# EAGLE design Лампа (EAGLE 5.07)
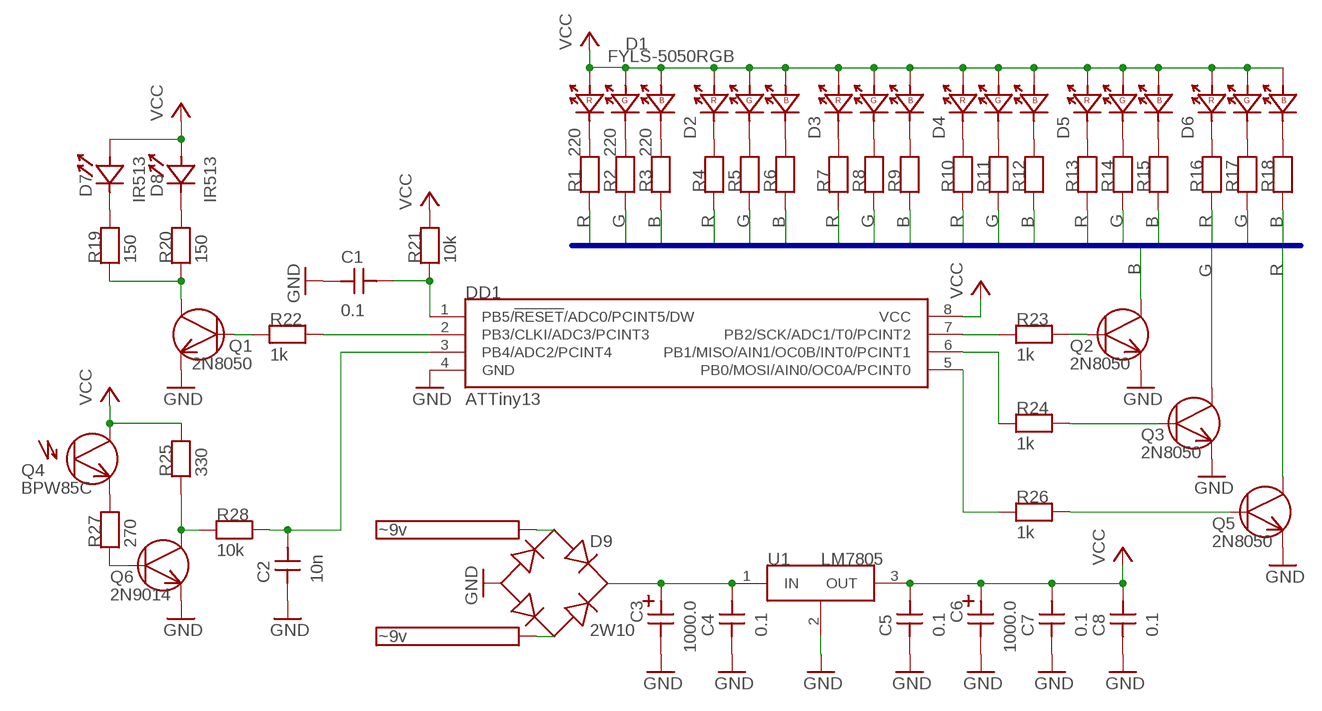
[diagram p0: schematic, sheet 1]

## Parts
C1  0.1  CAPACITOR_0805  [0805]
C2  10n  CAPACITOR_0805  [0805]
C3  1000.0  CAPACITOR_POLAR5,08_H1  [CAPACITOR_POLAR_5,08_H1]
C4  0.1  CAPACITOR_0805  [0805]
C5  0.1  CAPACITOR_0805  [0805]
C6  1000.0  CAPACITOR_POLAR5,08_H2  [CAPACITOR_POLAR_5,08_H2]
C7  0.1  CAPACITOR_0805  [0805]
C8  0.1  CAPACITOR_0805  [0805]
D1  FYLS-5050RGB  LED_FYLS-5050RGB  [LED_FYLS-5050RGB]
D2  LED_FYLS-5050RGB  [LED_FYLS-5050RGB]
D3  LED_FYLS-5050RGB  [LED_FYLS-5050RGB]
D4  LED_FYLS-5050RGB  [LED_FYLS-5050RGB]
D5  LED_FYLS-5050RGB  [LED_FYLS-5050RGB]
D6  LED_FYLS-5050RGB  [LED_FYLS-5050RGB]
D7  IR513  LED_5MM  [LED_5MM]
D8  IR513  LED_5MM  [LED_5MM]
D9  2W10  DIODE_BRIDGE  [DIODE_BRIDGE]
DD1  ATTiny13  ATTINY13  [DIL08]
PIN1  ~9v  PIN_NONAME  [PIN]
PIN2  ~9v  PIN_NONAME  [PIN]
Q1  2N8050  TRANSISTOR_NPN_TO92_EBC  [TO92]
Q2  2N8050  TRANSISTOR_NPN_TO92_EBC  [TO92]
Q3  2N8050  TRANSISTOR_NPN_TO92_EBC  [TO92]
Q4  BPW85C  BPW85  [BPW85]
Q5  2N8050  TRANSISTOR_NPN_TO92_EBC  [TO92]
Q6  2N9014  TRANSISTOR_NPN_TO92_EBC  [TO92]
R1  220  RESISTOR_0805  [0805]
R2  220  RESISTOR_0805  [0805]
R3  220  RESISTOR_0805  [0805]
R4  RESISTOR_0805  [0805]
R5  RESISTOR_0805  [0805]
R6  RESISTOR_0805  [0805]
R7  RESISTOR_0805  [0805]
R8  RESISTOR_0805  [0805]
R9  RESISTOR_0805  [0805]
R10  RESISTOR_0805  [0805]
R11  RESISTOR_0805  [0805]
R12  RESISTOR_0805  [0805]
R13  RESISTOR_0805  [0805]
R14  RESISTOR_0805  [0805]
R15  RESISTOR_0805  [0805]
R16  RESISTOR_0805  [0805]
R17  RESISTOR_0805  [0805]
R18  RESISTOR_0805  [0805]
R19  150  RESISTOR_0805  [0805]
R20  150  RESISTOR_HORIZONTAL  [RESISTOR_HORIZ]
R21  10k  RESISTOR_0805  [0805]
R22  1k  RESISTOR_HORIZONTAL  [RESISTOR_HORIZ]
R23  1k  RESISTOR_VERTICAL  [RESISTOR_VERT]
R24  1k  RESISTOR_VERTICAL  [RESISTOR_VERT]
R25  330  RESISTOR_VERTICAL  [RESISTOR_VERT]
R26  1k  RESISTOR_VERTICAL  [RESISTOR_VERT]
R27  270  RESISTOR_0805  [0805]
R28  10k  RESISTOR_VERTICAL  [RESISTOR_VERT]
U1  LM7805  LM78XX/LM79XX_78XX_D2PACK_2  [D2PACK_2]

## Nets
B: Q2.3(COLLECTOR) R3.1 R6.1 R9.1 R12.1 R15.1 R18.1
G: Q3.3(COLLECTOR) R2.1 R5.1 R8.1 R11.1 R14.1 R17.1
GND: C1.1 C2.1 C3.MINUS C4.1 C5.1 C6.MINUS C7.1 C8.1 D9.- DD1.4(GND) Q1.1(EMITTER) Q2.1(EMITTER) Q3.1(EMITTER) Q5.1(EMITTER) Q6.1(EMITTER) U1.2(GND)
N$1: C1.2 DD1.1(PB5/!RESET!/ADC0/PCINT5/DW) R21.1
N$2: Q1.2(BASE) R22.1
N$3: DD1.2(PB3/CLKI/ADC3/PCINT3) R22.2
N$4: Q1.3(COLLECTOR) R19.1 R20.1
N$5: D7.CATODE R19.2
N$6: D8.CATODE R20.2
N$7: Q4.E(EMITTER) R27.2
N$8: Q6.2(BASE) R27.1
N$9: Q6.3(COLLECTOR) R25.1 R28.1
N$10: D1.RC R1.2
N$11: C2.2 DD1.3(PB4/ADC2/PCINT4) R28.2
N$12: DD1.7(PB2/SCK/ADC1/T0/PCINT2) R23.1
N$13: Q2.2(BASE) R23.2
N$14: DD1.6(PB1/MISO/AIN1/OC0B/INT0/PCINT1) R24.1
N$15: Q3.2(BASE) R24.2
N$16: DD1.5(PB0/MOSI/AIN0/OC0A/PCINT0) R26.1
N$17: Q5.2(BASE) R26.2
N$18: D1.GC R2.2
N$19: D1.BC R3.2
N$20: D2.RC R4.2
N$21: D2.GC R5.2
N$22: D2.BC R6.2
N$23: D3.RC R7.2
N$24: D3.GC R8.2
N$25: D3.BC R9.2
N$26: D4.RC R10.2
N$27: D4.GC R11.2
N$28: D4.BC R12.2
N$29: D5.RC R13.2
N$30: D5.GC R14.2
N$31: D5.BC R15.2
N$32: D6.RC R16.2
N$33: D6.GC R17.2
N$34: D9.AC1 PIN1.P$1
N$35: D9.AC2 PIN2.P$1
N$36: C3.PLUS C4.2 D9.+ U1.1(IN)
N$37: D6.BC R18.2
R: Q5.3(COLLECTOR) R1.1 R4.1 R7.1 R10.1 R13.1 R16.1
VCC: C5.2 C6.PLUS C7.2 C8.2 D1.BA D1.GA D1.RA D2.BA D2.GA D2.RA D3.BA D3.GA D3.RA D4.BA D4.GA D4.RA D5.BA D5.GA D5.RA D6.BA D6.GA D6.RA D7.ANODE D8.ANODE DD1.8(VCC) Q4.C(COLLECTOR) R21.2 R25.2 U1.3(OUT)

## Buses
BUS:R,G,B

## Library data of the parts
C1 C2 C4 C5 C7 C8 = Len9:CAPACITOR
C3 C6 = Len9:CAPACITOR_POLAR
D1-D6 = Len9:LED_FYLS-5050RGB
D7 D8 = Len9:LED
D9 = Len9:DIODE_BRIDGE
DD1 = Len9:ATTINY13
PIN1 PIN2 = Len9:PIN_NONAME
Q1-Q3 Q5 Q6 = Len9:TRANSISTOR_NPN
Q4 = Len9:BPW85
R1-R28 = Len9:RESISTOR
U1 = Len9:LM78XX/LM79XX

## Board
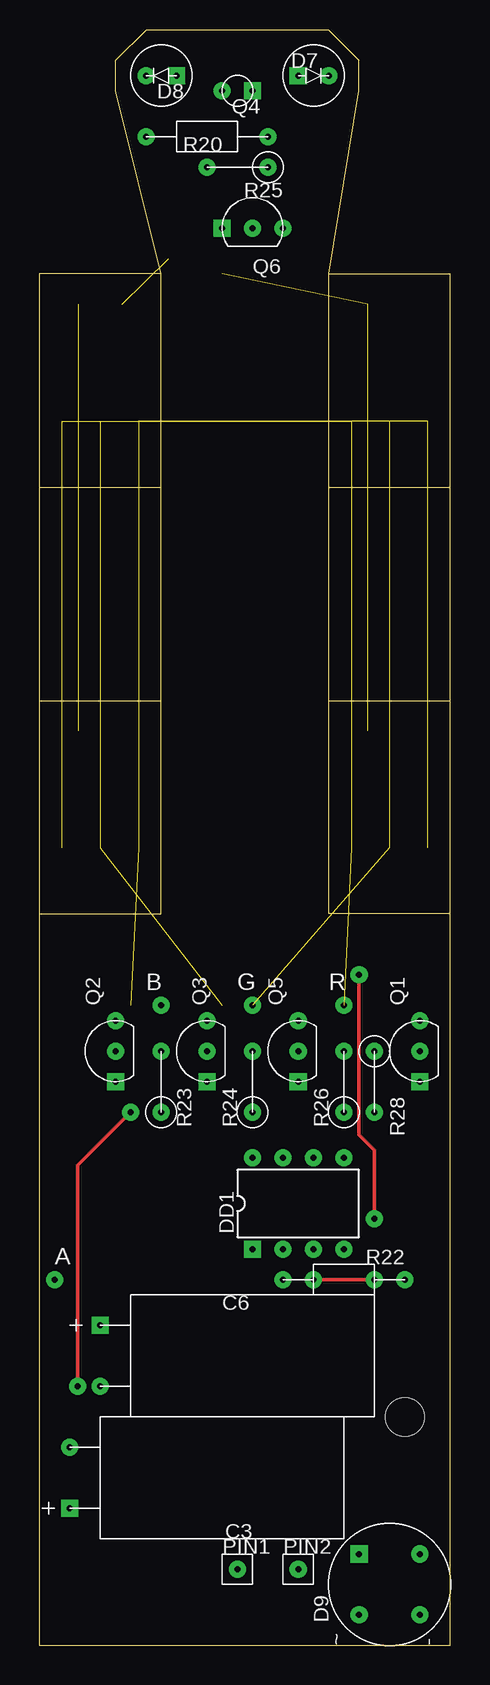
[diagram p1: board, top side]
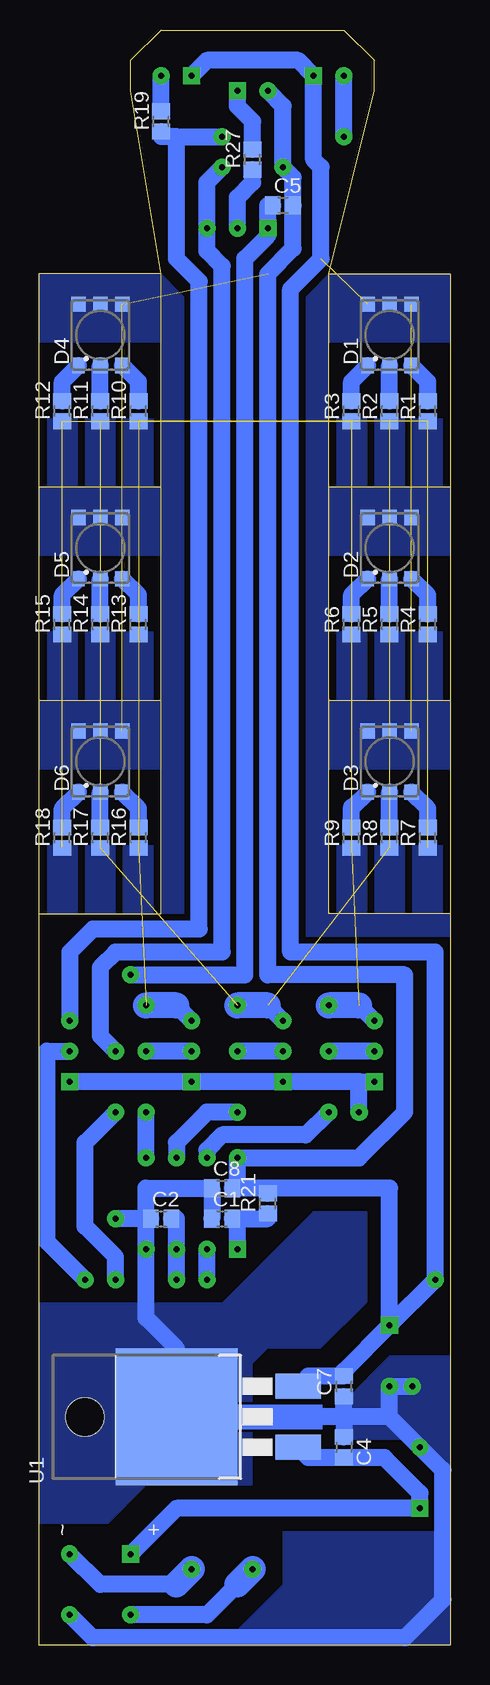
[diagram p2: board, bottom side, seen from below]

Size 34.29 x 134.62 mm. Coordinates in mm from the lower left corner, seen from the top.
Outline: 34.29,60.96 34.29,0 0,0 0,60.96
Outline: 34.29,60.96 34.29,78.74
Outline: 34.29,78.74 34.29,96.52
Outline: 34.29,96.52 34.29,114.3 24.13,114.3
Outline: 0,96.52 0,114.3 10.16,114.3
Outline: 0,96.52 0,78.74
Outline: 0,78.74 0,60.96
Outline: 0,60.96 10.16,60.96 10.16,78.74
Outline: 10.16,78.74 10.16,96.52
Outline: 10.16,96.52 10.16,114.3
Outline: 0,96.52 10.16,96.52
Outline: 0,78.74 10.16,78.74
Outline: 34.29,60.96 24.13,60.96 24.13,78.74
Outline: 24.13,78.74 24.13,96.52
Outline: 24.13,96.52 24.13,114.3
Outline: 24.13,96.52 34.29,96.52
Outline: 24.13,78.74 34.29,78.74
Outline: 10.16,114.3 6.35,129.54 6.35,132.08 8.89,134.62 24.13,134.62 26.67,132.08 26.67,129.54 24.13,114.3
Copper layers (1*16): Top 0.035mm / dielectric 1.5mm / Bottom 0.035mm
Design rules "default *": minimum track width 10mil, minimum drill 24mil, track to track 8mil, track to pad 8mil, pad to pad 8mil, via to via 8mil, smd to smd 8mil, copper to edge 0mil, drill to drill 8mil, minimum pad ring 10mil, minimum via ring 8mil, stop-mask expansion 4mil, vias tented up to drill 0mil, thermal gap 10mil

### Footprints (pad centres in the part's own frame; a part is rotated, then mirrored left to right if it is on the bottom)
0805 = smd 1.3 x 1.5: 1 -0.85,0; 2 0.85,0
CAPACITOR_POLAR_5,08_H1 = drill 0.5 pad 1.422 round: MINUS 2.54,0 | drill 0.5 pad 1.422 square: PLUS -2.54,0
CAPACITOR_POLAR_5,08_H2 = drill 0.5 pad 1.422 round: MINUS 2.54,0 | drill 0.5 pad 1.422 square: PLUS -2.54,0
LED_FYLS-5050RGB = smd 1.27 x 1.2: BA 2.55,1.825; GA 2.55,0; GC -2.55,0; RA 2.55,-1.825; RC -2.55,-1.825 | smd 1.27 x 1.05: BC -2.55,1.825
LED_5MM = drill 0.5 pad 1.422 square: ANODE -1.27,0 | drill 0.5 pad 1.422 round: CATODE 1.27,0
DIODE_BRIDGE = drill 0.5 pad 1.422 square: + 2.54,2.54 | drill 0.5 pad 1.422 round: - -2.54,-2.54; AC1 -2.54,2.54; AC2 2.54,-2.54
DIL08 = drill 0.5 pad 1.422 square: 1 -3.81,-3.81 | drill 0.5 pad 1.422 round: 2 -1.27,-3.81; 3 1.27,-3.81; 4 3.81,-3.81; 5 3.81,3.81; 6 1.27,3.81; 7 -1.27,3.81; 8 -3.81,3.81
PIN = drill 0.5 pad 1.422 round: P$1 0,0
TO92 = drill 0.5 pad 1.422 square: 1 -2.54,0 | drill 0.5 pad 1.422 round: 2 0,0; 3 2.54,0
BPW85 = drill 0.5 pad 1.422 round: C 1.27,0 | drill 0.5 pad 1.422 square: E -1.27,0
RESISTOR_HORIZ = drill 0.5 pad 1.422 round: 1 -5.08,0; 2 5.08,0
RESISTOR_VERT = drill 0.5 pad 1.422 round: 1 -2.54,0; 2 2.54,0
D2PACK_2 = smd 2.083 x 3.81: 1 -2.54,-10.16; 3 2.54,-10.16 | smd 11.43 x 10.16: 2 0,0 | hole 3.2: 0,7.62

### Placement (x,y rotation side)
C1  19.05,35.56 0 bottom
C2  24.13,35.56 0 bottom
C3  2.54,13.97 90 top
C4  8.89,16.51 270 bottom
C5  13.97,120.02 0 bottom
C6  5.08,24.13 270 top
C7  8.89,21.59 90 bottom
C8  19.05,38.1 0 bottom
D1  5.08,109.22 90 bottom
D2  5.08,91.44 90 bottom
D3  5.08,73.66 90 bottom
D4  29.21,109.22 90 bottom
D5  29.21,91.44 90 bottom
D6  29.21,73.66 90 bottom
D7  22.86,130.81 0 top
D8  10.16,130.81 180 top
D9  29.21,5.08 90 top
DD1  21.59,36.83 0 top
PIN1  16.51,6.35 0 top
PIN2  21.59,6.35 0 top
Q1  31.75,49.53 90 top
Q2  6.35,49.53 90 top
Q3  13.97,49.53 90 top
Q4  16.51,129.54 180 top
Q5  21.59,49.53 90 top
Q6  17.78,118.11 0 top
R1  1.91,102.87 90 bottom
R2  5.08,102.87 90 bottom
R3  8.26,102.87 90 bottom
R4  1.91,85.09 90 bottom
R5  5.08,85.09 90 bottom
R6  8.26,85.09 90 bottom
R7  1.91,67.31 90 bottom
R8  5.08,67.31 90 bottom
R9  8.26,67.31 90 bottom
R10  26.04,102.87 90 bottom
R11  29.21,102.87 90 bottom
R12  32.38,102.87 90 bottom
R13  26.04,85.09 90 bottom
R14  29.21,85.09 90 bottom
R15  32.38,85.09 90 bottom
R16  26.04,67.31 90 bottom
R17  29.21,67.31 90 bottom
R18  32.38,67.31 90 bottom
R19  24.13,127 90 bottom
R20  13.97,125.73 180 top
R21  15.24,36.83 90 bottom
R22  25.4,30.48 180 top
R23  10.16,46.99 90 top
R24  17.78,46.99 90 top
R25  16.51,123.19 180 top
R26  25.4,46.99 90 top
R27  16.51,123.83 90 bottom
R28  27.94,46.99 270 top
U1  22.86,19.05 90 bottom

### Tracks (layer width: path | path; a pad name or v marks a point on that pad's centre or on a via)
B  (via drill 0.5 pad 1.42)  (6 unrouted)
  Bottom 1.422: Q2.3 7.62,53.34
  Bottom 2.184: 7.62,53.34 v10.16,53.34
  pour Bottom (no thermals): 6.99,66.67 9.53,66.67 9.53,60.96 6.99,60.96
  pour Bottom (no thermals): 6.99,84.45 9.53,84.45 9.53,78.74 6.99,78.74
  pour Bottom (no thermals): 31.11,66.67 33.66,66.67 33.66,60.96 31.11,60.96
  pour Bottom (no thermals): 31.11,84.45 33.66,84.45 33.66,78.74 31.11,78.74
  pour Bottom (no thermals): 6.99,102.23 9.53,102.23 9.53,96.52 6.99,96.52
  pour Bottom (no thermals): 31.11,102.23 33.66,102.23 33.66,96.52 31.11,96.52
G  (via drill 0.5 pad 1.42)  (6 unrouted)
  Bottom 1.422: Q3.3 15.24,53.34
  Bottom 2.184: 15.24,53.34 v17.78,53.34
  pour Bottom (no thermals): 3.81,66.67 6.35,66.67 6.35,60.96 3.81,60.96
  pour Bottom (no thermals): 3.81,84.45 6.35,84.45 6.35,78.74 3.81,78.74
  pour Bottom (no thermals): 27.94,66.67 30.48,66.67 30.48,60.96 27.94,60.96
  pour Bottom (no thermals): 27.94,84.45 30.48,84.45 30.48,78.74 27.94,78.74
  pour Bottom (no thermals): 3.81,102.23 6.35,102.23 6.35,96.52 3.81,96.52
  pour Bottom (no thermals): 27.94,102.23 30.48,102.23 30.48,96.52 27.94,96.52
GND  (via drill 0.5 pad 1.42)
  Top 0.305: v27.94,35.56 27.94,41.27 26.67,42.55 v26.67,55.88 | v3.17,21.59 3.17,40.01 v7.62,44.45
  Bottom 1.422: C2.1 25.4,35.56 DD1.4 25.4,27.3 22.86,24.77 U1.2 8.89,19.05 | C1.1 C8.1 25.4,38.1 25.4,35.98 C2.1 | 8.89,19.05 C4.1 | 8.89,19.05 C7.1 | C5.1 15.24,120.02 Q6.1 15.24,117.47 17.14,115.57 17.14,55.88 v26.67,55.88 | C2.1 v27.94,35.56 | Q1.1 Q5.1 Q3.1 7.62,46.99 | 7.62,46.99 Q2.1 | v3.17,21.59 C6.MINUS 5.08,19.05 | v7.62,44.45 7.62,46.99 | D9.- 29.84,0.64 3.81,0.64 0.64,3.81 0.64,14.61 C3.MINUS 5.08,19.05 | 5.08,19.05 8.89,19.05
  pour Bottom (no thermals): 0,14.61 0,24.13 5.08,24.13 8.89,20.32 8.89,17.14 3.81,17.14 1.27,14.61
  pour Bottom (no thermals): 0,9.53 13.97,9.53 13.97,5.08 19.05,0 0,0
  pour Bottom (no thermals): 16.51,13.34 25.4,13.34 28.57,10.16 34.29,10.16 34.29,28.57 19.05,28.57 11.43,36.2 6.99,36.2 6.99,28.57 10.79,24.77 15.24,24.77 16.51,23.5
N$1
  Bottom 1.422: R21.1 15.24,35.56 C1.2 17.78,35.14 DD1.1
N$2
  Bottom 1.422: Q1.2 33.66,49.53 33.66,33.66 R22.1
N$3
  Bottom 1.422: R22.2 DD1.2
N$4
  Bottom 1.422: R19.1 24.13,125.73 22.86,125.73 | 22.86,125.73 R20.1 | Q1.3 31.75,57.78 29.84,59.69 20.95,59.69 20.95,113.67 22.86,115.57 22.86,125.73
N$5
  Bottom 1.422: R19.2 D7.CATODE
N$6
  Bottom 1.422: R20.2 D8.CATODE
N$7
  Bottom 1.422: Q4.E 17.78,128.27 16.51,127 R27.2
N$8
  Bottom 1.422: Q6.2 17.78,120.65 16.51,121.92 R27.1
N$9
  Bottom 1.422: R25.1 20.32,121.92 Q6.3 20.32,116.2 19.05,114.94 19.05,57.78 27.94,57.78 29.21,56.52 29.21,50.8 R28.1
N$10
  Bottom 1.422: D1.RC 1.91,105.32 R1.2
N$11  (via drill 0.5 pad 1.42)
  Top 0.305: v22.86,30.48 v27.94,30.48
  Bottom 1.422: C2.2 22.86,35.56 DD1.3 v22.86,30.48 | v27.94,30.48 27.94,32.38 30.48,34.92 30.48,41.91 R28.2
N$12
  Bottom 1.422: DD1.7 20.32,41.27 19.05,42.55 12.06,42.55 R23.1
N$13
  Bottom 1.422: Q2.2 R23.2
N$14
  Bottom 1.422: DD1.6 22.86,41.91 20.32,44.45 R24.1
N$15
  Bottom 1.422: Q3.2 R24.2
N$16
  Bottom 1.422: DD1.5 R26.1
N$17
  Bottom 1.422: Q5.2 R26.2
N$18
  Bottom 1.422: R2.2 D1.GC
N$19
  Bottom 1.422: D1.BC 8.26,105.32 R3.2
N$20
  Bottom 1.422: D2.RC 1.91,87.54 R4.2
N$21
  Bottom 1.422: R5.2 D2.GC
N$22
  Bottom 1.422: D2.BC 8.26,87.54 R6.2
N$23
  Bottom 1.422: D3.RC 1.91,69.76 R7.2
N$24
  Bottom 1.422: R8.2 D3.GC
N$25
  Bottom 1.422: D3.BC 8.16,69.85 8.26,69.85 R9.2
N$26
  Bottom 1.422: D4.RC 26.04,105.32 R10.2
N$27
  Bottom 1.422: R11.2 D4.GC
N$28
  Bottom 1.422: D4.BC 32.38,105.32 R12.2
N$29
  Bottom 1.422: D5.RC 26.04,87.54 R13.2
N$30
  Bottom 1.422: R14.2 D5.GC
N$31
  Bottom 1.422: D5.BC 32.38,87.54 R15.2
N$32
  Bottom 1.422: D6.RC 26.04,69.76 R16.2
N$33
  Bottom 1.422: R17.2 D6.GC
N$34
  Bottom 1.422: 17.78,5.08 20.32,2.54 D9.AC1
  Bottom 2.184: PIN1.P$1 17.78,5.08
N$35
  Bottom 1.422: 22.86,5.08 29.21,5.08 D9.AC2
  Bottom 2.184: PIN2.P$1 22.86,5.08
N$36
  Bottom 1.422: U1.1 11.85,15.66 C4.2 5.5,15.66 2.54,12.7 C3.PLUS 22.86,11.43 D9.+
N$37
  Bottom 1.422: D6.BC 32.38,69.76 R18.2
N$38
  pour Bottom: 10.16,114.3 12.06,112.39 12.06,59.05 0,59.05 0,60.96 10.16,60.96
N$39
  pour Bottom: 24.13,114.3 22.23,112.39 22.23,60.96 24.13,60.96
R  (via drill 0.5 pad 1.42)  (6 unrouted)
  Bottom 1.422: Q5.3 22.86,53.34
  Bottom 2.184: 22.86,53.34 v25.4,53.34
  pour Bottom (no thermals): 0.64,66.67 3.17,66.67 3.17,60.96 0.64,60.96
  pour Bottom (no thermals): 0.64,84.45 3.17,84.45 3.17,78.74 0.64,78.74
  pour Bottom (no thermals): 24.77,66.67 27.3,66.67 27.3,60.96 24.77,60.96
  pour Bottom (no thermals): 24.77,84.45 27.3,84.45 27.3,78.74 24.77,78.74
  pour Bottom (no thermals): 0.64,102.23 3.17,102.23 3.17,96.52 0.64,96.52
  pour Bottom (no thermals): 24.77,102.23 27.3,102.23 27.3,96.52 24.77,96.52
VCC  (via drill 0.5 pad 1.42)  (6 unrouted)
  Bottom 1.422: 15.24,38.1 C8.2 17.78,38.1 DD1.8 7.62,40.64 3.81,44.45 3.81,55.88 15.24,55.88 15.24,114.3 13.12,116.42 C5.2 13.12,122.34 R25.2 13.97,128.27 Q4.C | U1.3 11.85,22.44 C7.2 8.89,22.86 C6.PLUS | 15.24,38.1 R21.2 | C6.PLUS 5.08,38.1 15.24,38.1 | D7.ANODE 20.32,132.08 12.7,132.08 D8.ANODE 11.43,123.83 10.79,123.19 10.79,115.57 13.34,113.03 13.34,57.78 1.27,57.78 v1.27,30.48 C6.PLUS
  pour Bottom (no thermals): 0,78.74 10.16,78.74 10.16,73.03 0,73.03
  pour Bottom (no thermals): 0,96.52 10.16,96.52 10.16,90.81 0,90.81
  pour Bottom (no thermals): 24.13,78.74 34.29,78.74 34.29,73.03 24.13,73.03
  pour Bottom (no thermals): 24.13,96.52 34.29,96.52 34.29,90.81 24.13,90.81
  pour Bottom (no thermals): 0,114.3 10.16,114.3 10.16,108.58 0,108.58
  pour Bottom (no thermals): 24.13,114.3 34.29,114.3 34.29,108.58 24.13,108.58

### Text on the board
tNames: B | G | R | A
